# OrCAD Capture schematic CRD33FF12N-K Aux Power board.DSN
size C; title: 60kW Three-phase Interleaved DCDC; rev: 0v1; note: P/N: CRD-60DD12N-K
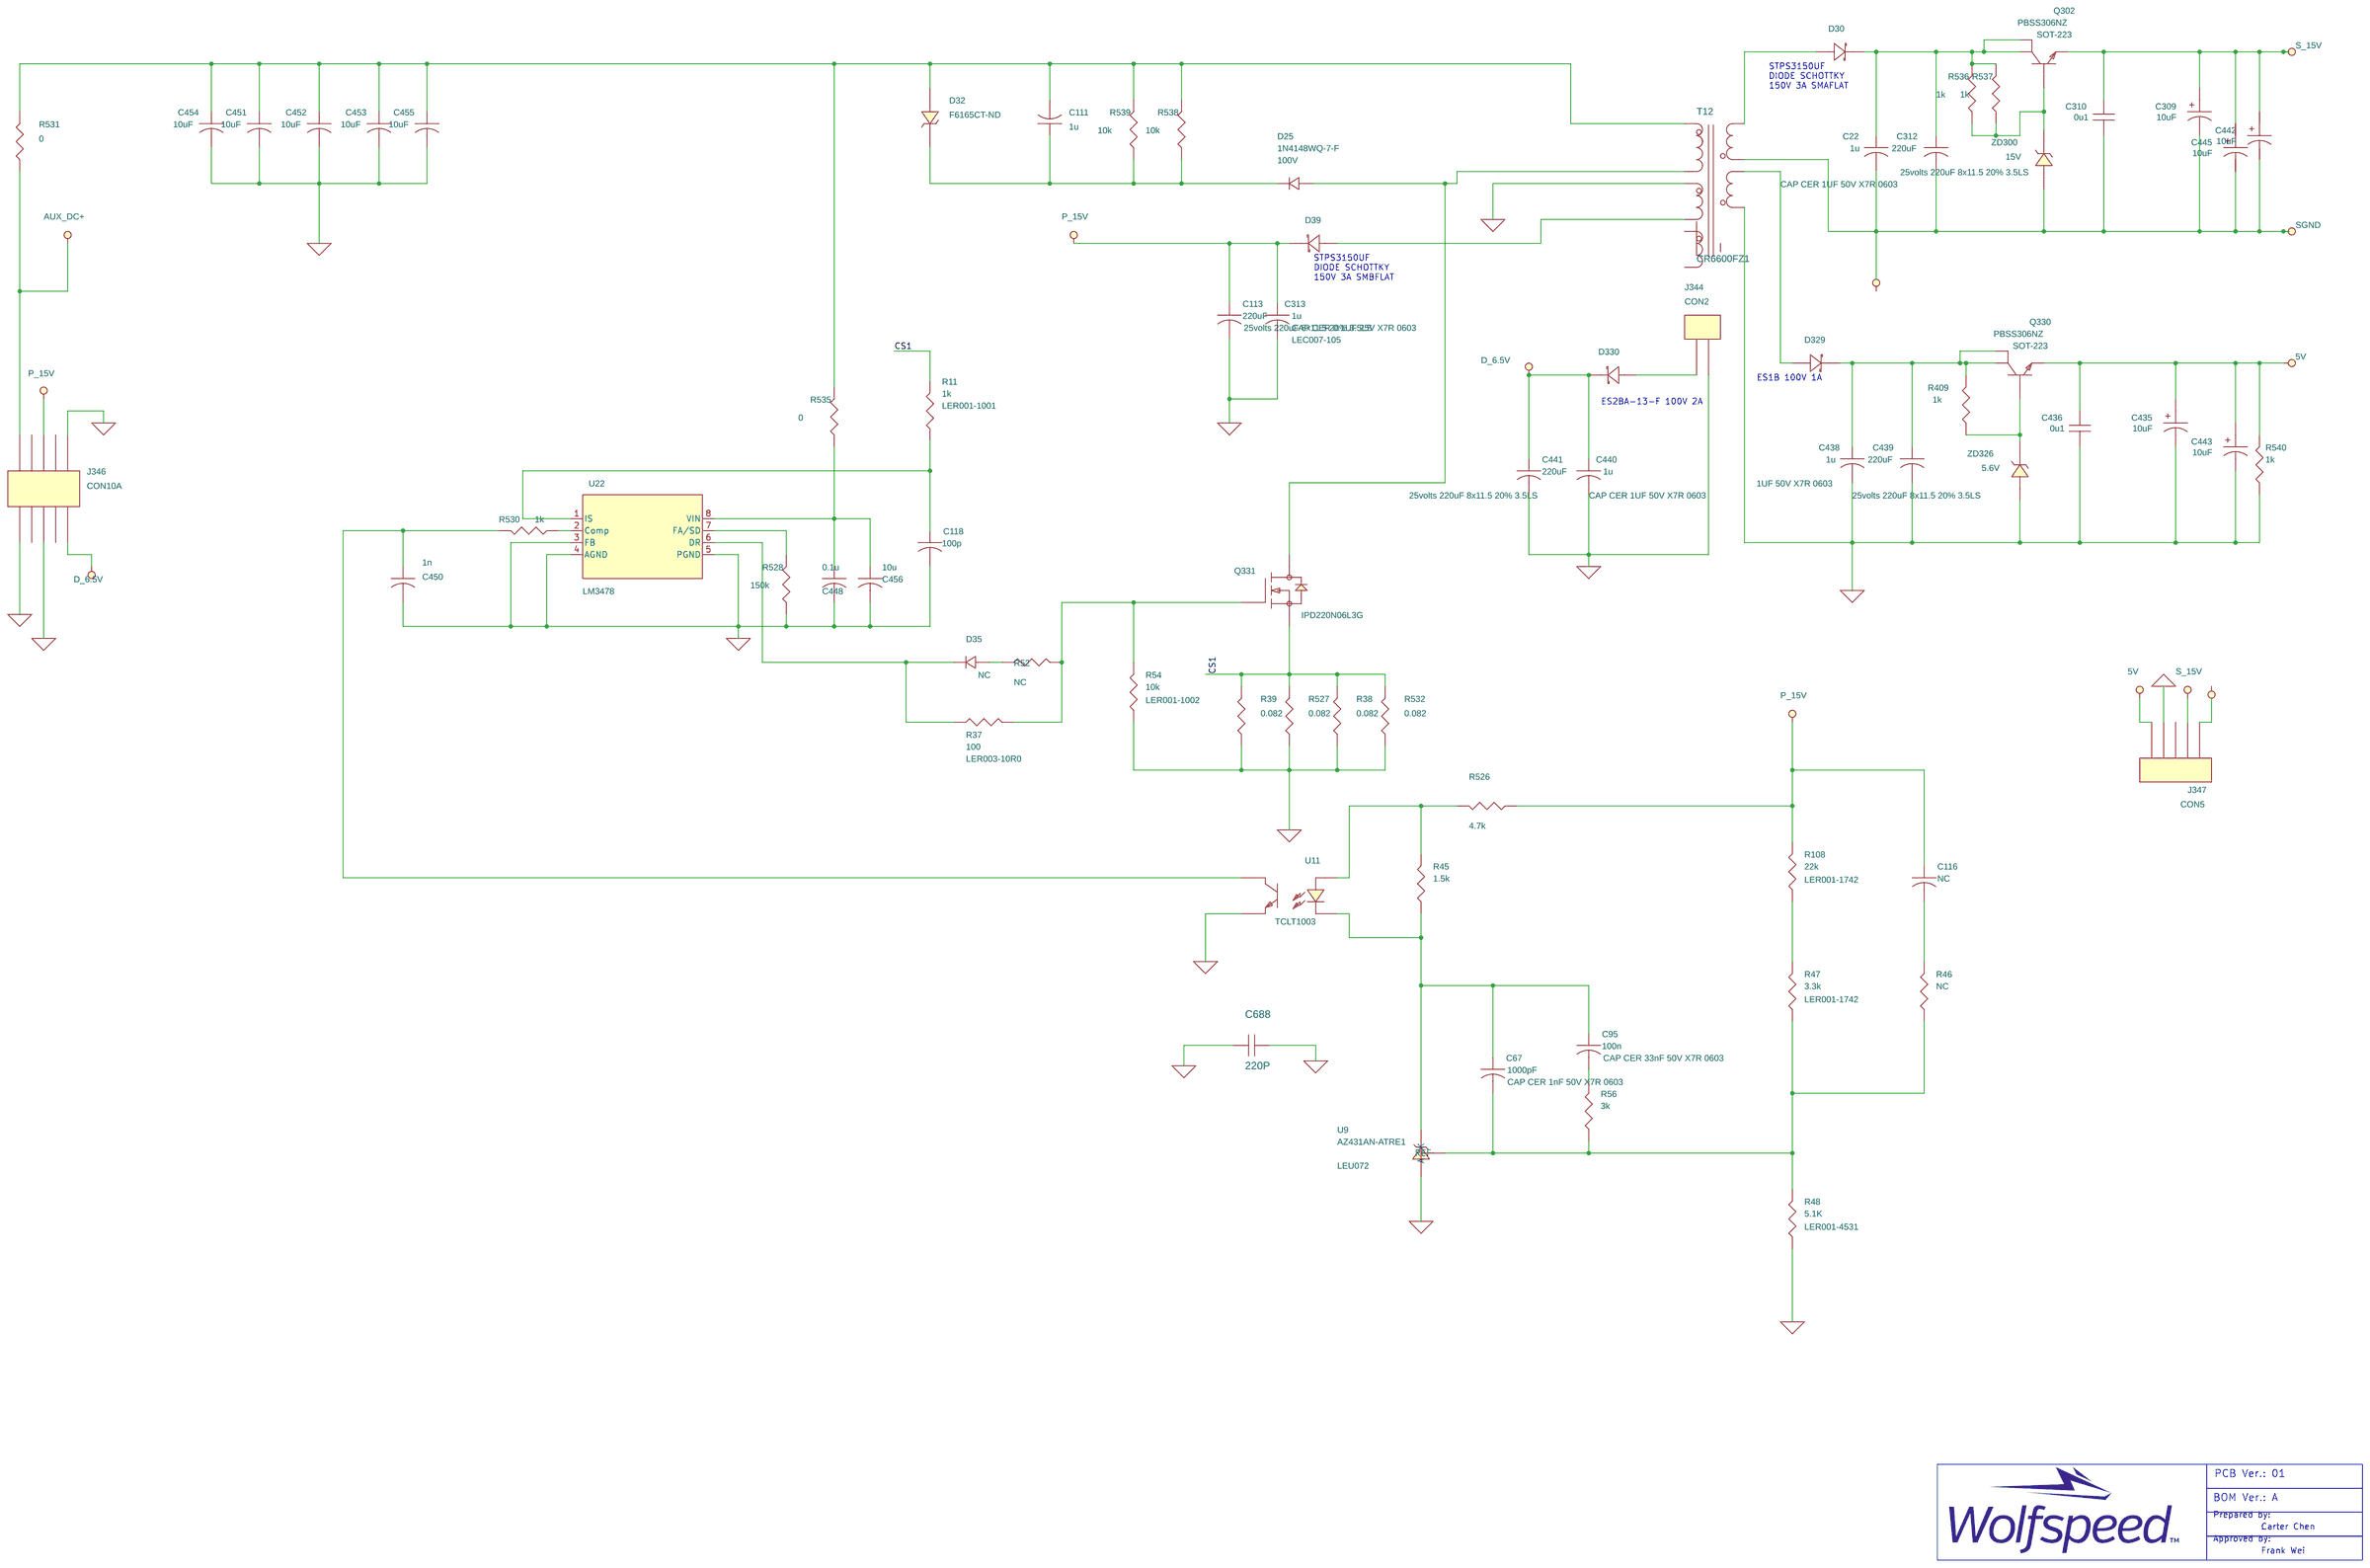
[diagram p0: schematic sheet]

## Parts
C22  1u  [C0603]
C67  1000pF  [c0603]
C95  100n  [c0603]
C111  1u  [C1206]
C113  220uF  [c220u25v]
C116  NC  [C0603]
C118  100p  [c0603]
C309  10uF  [C1206]
C310  0u1  [C0603]
C312  220uF  [c220u25v]
C313  1u  [C0603]
C435  10uF  [C1206]
C436  0u1  [C0603]
C438  1u  [C0603]
C439  220uF  [c220u25v]
C440  1u  [C0603]
C441  220uF  [c220u25v]
C442  10uF  [C1206]
C443  10uF  [C1206]
C445  10uF  [C1206]
C448  0.1u  [c0603]
C450  1n  [c0603]
C451  10uF  [c1206]
C452  10uF  [c1206]
C453  10uF  [c1206]
C454  10uF  [c1206]
C455  10uF  [c1206]
C456  10u  [C1206]
C688  220P  [Y1]
D25  1N4148WQ-7-F  [SMA]
D30  LED277_SCHOTTKY_40V_3A_SMB  [SMB]
D32  F6165CT-ND  [SMA]
D35  NC  [SMA]
D39  150V_3A  [SMA]
D329  LED277_SCHOTTKY_40V_3A_SMB  [SMA]
D330  LED277_SCHOTTKY_40V_3A_SMB  [SMA]
J344  CON2  [CON_2MM54_2X1]
J346  CON10A  [con_2mm54_5x2]
J347  CON5  [CON_2MM54_5X1]
Q302  PBSS306NZ  [SOT-223]
Q330  PBSS306NZ  [SOT-223]
Q331  IPD220N06L3G  [to252AB]
R11  1k  [r0603]
R37  100  [r0805]
R38  0.082  [r1206]
R39  0.082  [r1206]
R45  1.5k  [r0603]
R46  NC  [R0603]
R47  3.3k  [R0603]
R48  5.1K  [R0603]
R52  NC  [r0805]
R54  10k  [r0603]
R56  3k  [r0603]
R108  22k  [R0603]
R409  1k  [R1206]
R526  4.7k  [r0603]
R527  0.082  [r1206]
R528  150k  [r0603]
R530  1k  [r0603]
R531  0  [r1206]
R532  0.082  [r1206]
R535  0  [r0603]
R536  1k  [R1206]
R537  1k  [R1206]
R538  10k  [R1206]
R539  10k  [R1206]
R540  1k  [R1206]
T12  CR6600FZ1  [TPRIAUX]
U9  AZ431AN-ATRE1  [SOT23_1-32]
U11  TCLT1003  [opto-sop-4l]
U22  LM3478  [SOIC8]
ZD300  15V  [SOD-123]
ZD326  5.6V  [SOD-123]

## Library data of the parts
C22 C440 = LEC007_0805_50V: LLF Part Number: LEC007-105; Type: Yageo; VOLTAGE: CAP CER 1UF 50V X7R 0603; value1: CC0603KRX7R9BB105
C67 = LEC007_0805_50V: LLF Part Number: LEC007-102; Type: Yageo; VOLTAGE: CAP CER 1nF 50V X7R 0603; value1: CC0603JRNPO9BN102
C95 C450 = LEC006_0603_50V: LLF Part Number: LEC006-333; Type: Yageo; VOLTAGE: CAP CER 33nF 50V X7R 0603; value1: CC0603KRX7R9BB333
C111 = LEC052_1206_0.033UF_630V: Type: Samsung; VOLTAGE: MLCC 3216(1206) X7R 33NF 10% 630
C113 C312 C439 C441 = LEC231_AL_470UF_25V_0: Type: nichicon; VOLTAGE: 25volts 220uF 8x11.5 20% 3.5LS; value1: UHE1E221MPD
C116 = LEC006_0603_50V: LLF Part Number: LEC006-104; Type: Yageo; VOLTAGE: CAP CER 0.1UF 25V X7R 0603; value1: CC0603KRX7R8BB104
C118 = LEC003_0603_16V: LLF Part Number: LEC003-101
C309 C435 C442 C443 C445 = CAP_POL: Type: Yageo; VOLTAGE: CAP CER 10UF 25V X7R 1206; value1: CC1206KKX7R8BB106
C310 C436 = CAP_NP: Type: Yageo; VOLTAGE: CAP CER 0.1UF 25V X7R 0603; value1: CC0603KRX7R8BB104
C313 = LEC007_0805_50V: LLF Part Number: LEC007-105; Type: Yageo; VOLTAGE: CAP CER 0.1UF 25V X7R 0603; value1: CC0603KRX7R8BB104
C438 = LEC007_0805_50V: LLF Part Number: LEC007-105; Type: Yageo; VOLTAGE: 1UF 50V X7R 0603; value1: CC0603KRX7R9BB105
C448 C456 = LEC006_0603_50V: LLF Part Number: LEC006-333; Type: Yageo; VOLTAGE: 33nF 50V; value1: CC0603KRX7R9BB333
C451-C455 = LEC034_AL_47UF_25V: LLF Part Number: LEC034; Type: Yageo; VOLTAGE: CAP CER 10UF 25V X7R 1206; value1: CC1206KKX7R8BB106
C688 = CAP_NP: value1: 800V
D25 D35 = LED005_1000V_1A_DO214AC_3: LLF Part Number: 100V; Type: ON; VOLTAGE: DIODE GEN PURP 600V 1A SOD123F; value1: ES1JFL
D30 D39 = LED277_SCHOTTKY_40V_3A_SMB_0: LLF Part Number: LEDXXX; Type: ST; VOLTAGE: DIODE SCHOTTKY 150V 3A SMBFLAT; value1: STPS3150UF
D32 = LED188_TVS_350V_600W_SMB_0: Type: Vishay
D329 = LED277_SCHOTTKY_40V_3A_SMB_0: LLF Part Number: LEDXXX; Type: Micro Commercial Co; VOLTAGE: DIODE SCHOTTKY 1A 60V SMA; value1: SS16-LTP
D330 = LED277_SCHOTTKY_40V_3A_SMB_0: LLF Part Number: LEDXXX; Type: Micro Commercial Co; VOLTAGE: DIODE SCHOTTKY 1A 100V SMA; value1: SS16-LTP
J344 = CON2: VOLTAGE: con2mm54_2x1
J346 = CON10A: VOLTAGE: con2mm_5x2
J347 = CON5: VOLTAGE: con2mm54_5x1
Q302 Q330 = NPN_BCE_1: Type: Nexperia USA Inc.; VOLTAGE: TRANS NPN 100V 5.1A; value1: PBSS306NZ,135
Q331 = 2N7002_SOT_1
R11 R530 = LER001_0603_1: Descriptiom: Resistor; LLF Part Number: LER001-1001
R37 = LER003_0805_1: LLF Part Number: LER003-10R0
R38 R39 R527 R531 R532 = LER003_0805_1: LLF Part Number: LER003-3R90
R45 = LER001_0603_1: LLF Part Number: LER001-1001
R46 = LER001_0603_1: LLF Part Number: LER001-1001; Type: Yageo; VOLTAGE: RES SMD 1K OHM 1% 1/10W 0603; value1: AC0603FR-071KL
R47 = LER001_0603_1: LLF Part Number: LER001-1742; Type: Yageo; VOLTAGE: RES SMD 1.5K OHM 1% 1/10W 0603; value1: AC0603FR-071K5L
R48 = LER001_0603_1: LLF Part Number: LER001-4531; Type: Yageo; VOLTAGE: RES SMD 4.7K OHM 1% 1/10W 0603; value1: RC0603FR-074K7L
R52 = LER003_0805_1: LLF Part Number: LER003-5R10
R54 = LER001_0603_1: LLF Part Number: LER001-1002
R56 = LER001_0603_1: LLF Part Number: LER001-8202
R108 = LER001_0603_1: LLF Part Number: LER001-1742; Type: Yageo; VOLTAGE: RES SMD 22K OHM 1% 1/10W 0603; value1: AC0603FR-0722KL
R409 R540 = R: Type: Yageo; VOLTAGE: RES SMD 4.7K OHM 1% 1/10W 0603; value1: RC0603FR-074K7L
R526 = LER005_1206_1: LLF Part Number: LER005-2204
R528 R535-R539 = LER001_0603_1: Descriptiom: Resistor; LLF Part Number: LER001-5102
T12 = CREE-6600-FZ1_5: Part number: 607200285; Type: Inductor
U9 = LEU094_ZTL431AFTA_SOT23_2: LLF Part Number: LEU072
U11 = LEU169_TCLT1003_SOP-4L
U22 = 1EDI60N12AF-DS_3
ZD300 = DIODE_ZENER
ZD326 = DIODE_ZENER: Type: Diodes; VOLTAGE: DIODE ZENER 5.1V 500MW SOD123; value1: MMSZ5231B-7-F

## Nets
5V: C435.1 C436.1 C443.1 J347.1 Q330.3(E) R540.1
DGND: C440.2 C441.1(2) J344.1 J346.10
PGND_SIGNAL: C113.1(2) C313.2 C688.1 J346.5 R48.1 T12.5 U9.1(A)
SGND: C22.2 C309.2 C310.2 C312.1(2) C442.2 C445.2 J347.5 T12.9 ZD300.1(ANODE)
AUX_DC+: J346.2 R531.1
CAN_GND: C435.2 C436.2 C438.2 C439.1(2) C443.2 J347.2 R540.2 T12.6 ZD326.1(ANODE)
CS1: Q331.A2(Source) R11.1 R38.2 R39.2 R527.2 R532.2
D_6.5V: C440.1 C441.2(1) D330.2(K) J346.9
ISGND: C118.2 C448.2 C450.2 C451.2 C452.2 C453.2 C454.2 C455.2 C456.2 C688.2 J346.1 R38.1 R39.1 R54.1 R527.1 R528.2 R532.1 U11.3 U22.3(FB) U22.4(AGND) U22.5(PGND)
P_15V: C113.2(1) C116.1 C313.1 D39.2(K) J346.6 R108.2 R526.1
S_15V: C309.1 C310.1 C442.1 C445.1 J347.4 Q302.3(E)
N16531834: D39.1(A) T12.4
N16531864: C111.2 C451.1 C452.1 C453.1 C454.1 C455.1 D32.1 R531.2 R535.1 R538.1 R539.1 T12.3
N16531900: C111.1 D25.2 D32.2 R538.2 R539.2
N16531954: D25.1 Q331.K(Drain) T12.1
N16531988: C22.1 C312.2(1) D30.2(K) Q302.2(C) Q302.4(C1) R536.1 R537.1
N16540909: Q302.1(B) R536.2 R537.2 ZD300.2(CATHODE)
N16668742: C438.1 C439.2(1) D329.2(K) Q330.2(C) Q330.4(C1) R409.1
N16669014: Q330.1(B) R409.2 ZD326.2(CATHODE)
N16669754: D329.1(A) T12.7
N16669797: D30.1(A) T12.10
N16867048: D330.1(A) J344.2
N16899196: C67.2 R46.1 R47.1 R48.2 R56.1 U9.3(REF)
N16899206: C116.2 R46.2
N16899220: R47.2 R108.1
N16900053: R45.2 R526.2 U11.1
N16900214: C67.1 C95.1 R45.1 U9.2(K) U11.2
N16900266: C95.2 R56.2
N16901051: C118.1 R11.2 U22.1(IS)
N16901170: D35.2 R37.1 U22.6(DR)
N16901172: Q331.A1(Gate) R37.2 R52.2 R54.2
N16903870: D35.1 R52.1
N16903956: R528.1 U22.7(FA/SD)
N16904160: C448.1 C456.1 R535.2 U22.8(VIN)
N16915016: R530.2 U22.2(Comp)
N16915019: C450.1 R530.1 U11.4

Not connected (* = marked no-connect by the designer): J346 3 4 7 8; J347 3; T12 2 8

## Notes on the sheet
- STPS3150UF
  DIODE SCHOTTKY
  150V 3A SMAFLAT
- STPS3150UF
  DIODE SCHOTTKY
  150V 3A SMBFLAT
- ES1B 100V 1A
- ES2BA-13-F 100V 2A
- PCB Ver.: 01
- BOM Ver.: A
- Prepared by:
- .
- Carter Chen
- Approved by:
- Frank Wei
